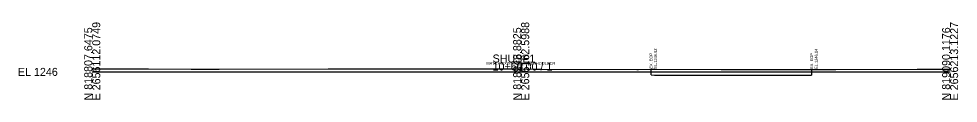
# Model space of a CAD drawing. Extents: x -26 to 401, y -21 to 6517.
# Drawn here: x -25.7 to 302.8, y 5990.3 to 6017.3 of the extents above; entities that cross this region are included whole.
import ezdxf

# ---------------------------------------------------------------- set-up
doc = ezdxf.new("R2010")
doc.units = 0
for name, color, linetype in [('DESIGN - SHEET - Light Grid', 7, 'Continuous'), ('DESIGN - TYPICAL - Text', 7, 'Continuous'), ('SURVEY - GROUND - Existing Pavement Layer', 7, 'Continuous'), ('SURVEY - GROUND - Existing Pavement Text', 7, 'Continuous'), ('SURVEY - GROUND - Top of Ground', 7, 'Continuous')]:
    doc.layers.add(name, color=color, linetype=linetype)

msp = doc.modelspace()

# ---------------------------------------------------------------- linework, layer by layer
at = {"layer": 'DESIGN - SHEET - Light Grid'}
for p, q in [((150, 6000), (150, 6003.28)), ((0, 6000), (150, 6000)), ((150, 6000), (300, 6000))]:
    msp.add_line(p, q, dxfattribs=at)
at = {"layer": 'SURVEY - GROUND - Existing Pavement Layer'}
for p, q in [((195.41, 5998.92), (195.41, 6000.92)), ((251.59, 6000.84), (251.59, 5998.84)), ((195.41, 5998.92), (196.57, 5998.91)), ((196.57, 5998.91), (219.96, 5998.85)), ((219.96, 5998.85), (229.33, 5998.85)), ((229.33, 5998.85), (250.44, 5998.84)), ((250.44, 5998.84), (250.99, 5998.84)), ((250.99, 5998.84), (251.59, 5998.84))]:
    msp.add_line(p, q, dxfattribs=at)
at = {"layer": 'SURVEY - GROUND - Top of Ground'}
msp.add_lwpolyline([(0, 6001.03), (11.63, 6001.04), (19.68, 6001.02), (34.62, 6001.01), (39.87, 6001), (43.09, 6000.99), (44.42, 6000.99), (82.46, 6001.09), (83.18, 6001.09), (115.98, 6001.09), (116.56, 6001.09), (128.7, 6001.07), (150, 6001.02), (155.04, 6001.01), (157.14, 6001), (190.5, 6000.87), (191, 6000.87), (195.41, 6000.92), (196.57, 6000.91), (219.96, 6000.85), (229.33, 6000.85), (250.44, 6000.84), (250.99, 6000.84), (251.59, 6000.84), (252.96, 6000.84), (258.84, 6000.87), (259.48, 6000.87), (260.04, 6000.88), (288.46, 6000.93), (289.83, 6000.92), (300, 6000.92)], dxfattribs=at)

# ---------------------------------------------------------------- texts
at = {"layer": 'DESIGN - SHEET - Light Grid'}
for s, p in [('N 818807.6475', (0, 5990)), ('E 2656112.0749', (2.8, 5990)), ('N 818948.8825', (150, 5990)), ('E 2656162.5988', (152.8, 5990)), ('N 819090.1176', (300, 5990)), ('E 2656213.1227', (302.8, 5990))]:
    msp.add_text(s, height=2.8, rotation=90, dxfattribs=at).set_placement(p)
for s, p in [('SHUSE1', (140, 6003.28)), ('10+60.00 / 1', (140, 6000.48)), ('EL 1246', (-26, 5998.6))]:
    msp.add_text(s, height=2.8, dxfattribs=at).set_placement(p)
at = {"layer": 'DESIGN - TYPICAL - Text'}
msp.add_text('MATCH EXISTING SR-63 SHOULDER', height=1, dxfattribs=at).set_placement((137.82, 6002.48))
at = {"layer": 'SURVEY - GROUND - Existing Pavement Text'}
for s, p in [('EX. EOP', (195.91, 6001.12)), ('EL.1246.92', (197.47, 6001.12)), ('EX. EOP', (252.09, 6001.04)), ('EL.1246.84', (253.68, 6001.04))]:
    msp.add_text(s, height=1, rotation=90, dxfattribs=at).set_placement(p)

doc.saveas('drawing.dxf')
